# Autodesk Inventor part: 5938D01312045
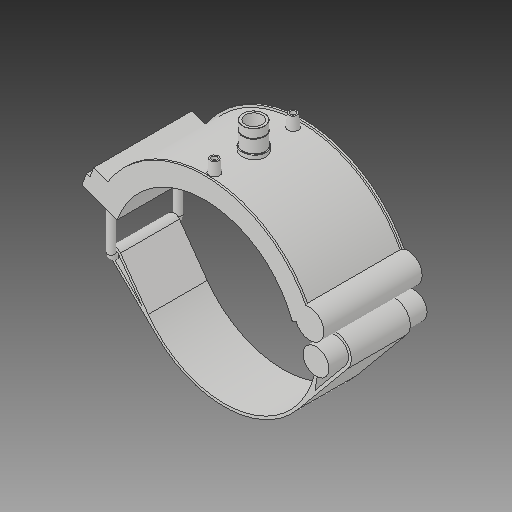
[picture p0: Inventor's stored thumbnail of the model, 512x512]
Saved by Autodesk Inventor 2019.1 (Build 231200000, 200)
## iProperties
Created: 2017-07
Part Number: 5938D01312045
Material: Generic
Description: PLASSON TRANSITION SADDLE 12''DIPS x 1"NPT
Document SubType Name: Modeling
Designer: KIM
Density: 1 g/cm^3
Appearance: Default
Author: KIM
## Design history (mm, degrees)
derived "5938D.ipt"
feature "Solid1::5938D.ipt"
tag "TaggingFeature1"
body "Solid1"
other parameters: "d_" = 333.8, "B_" = 194.818, "H_" = 46.736, "L_" = 176.022, "d_t" = 6, "G_" = 30.291, "d148" = 5.007, "d160" = 5.007, "d169" = 5.007, "d192" = 13.352, "d0" = 333.8, "d1" = 400.56, "d2" = 487.045, "d3" = 83.45, "d4" = 176.022, "d5" = 0, "d40" = 208.2912, "d41" = 42.4074, "d43" = 0, "d45" = 0, "d47" = 247.016, "d48" = 39.3783, "d50" = 0, "d78" = 222.28, "d79" = 15, "d80" = 70.4088, "d82" = 5 deg, "d84" = 4, "d85" = 14, "d86" = 0, "d87" = 3, "d88" = 0, "d96" = 408.5712, "d97" = 3.52044, "d98" = 0, "d102" = 0.90873, "d103" = 30.291, "d104" = 28.0416, "d105" = 0, "d106" = 24.2328, "d108" = 0, "d109" = -15.57867, "d111" = 0.5, "d112" = 0.5, "d113" = 0, "d114" = 0.5, "d117" = 0.30291, "d120" = 140 deg, "d121" = 24.228, "d122" = 20 deg, "d123" = 1602.24, "d124" = 240.336, "d126" = 0, "d143" = 343.814, "d145" = 51.35385, "d149" = 5.007, "d150" = 56.48923, "d153" = 176.022, "d154" = 0, "d156" = 200.28, "d157" = 160 deg, "d159" = 13.352, "d161" = 5.007, "d162" = 105.6132, "d163" = 0, "d164" = 166.9, "d167" = 33.38, "d168" = 195.39512, "d170" = 5.007, "d172" = 0, "d173" = 1, "d175" = 166.9, "d176" = 20 deg, "d177" = 23.366, "d178" = 66.76, "d180" = 0, "d183" = 26.704, "d184" = 18.6928, "d185" = 57.20715, "d186" = 57.20715, "d187" = 200.28, "d188" = 20.028, "d189" = 23.366, "d190" = 0, "d191" = 240.336, "d193" = 13.352, "d194" = 6.8429, "d195" = 90 deg, "d197" = 0, "d199" = 0
